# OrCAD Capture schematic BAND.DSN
size A
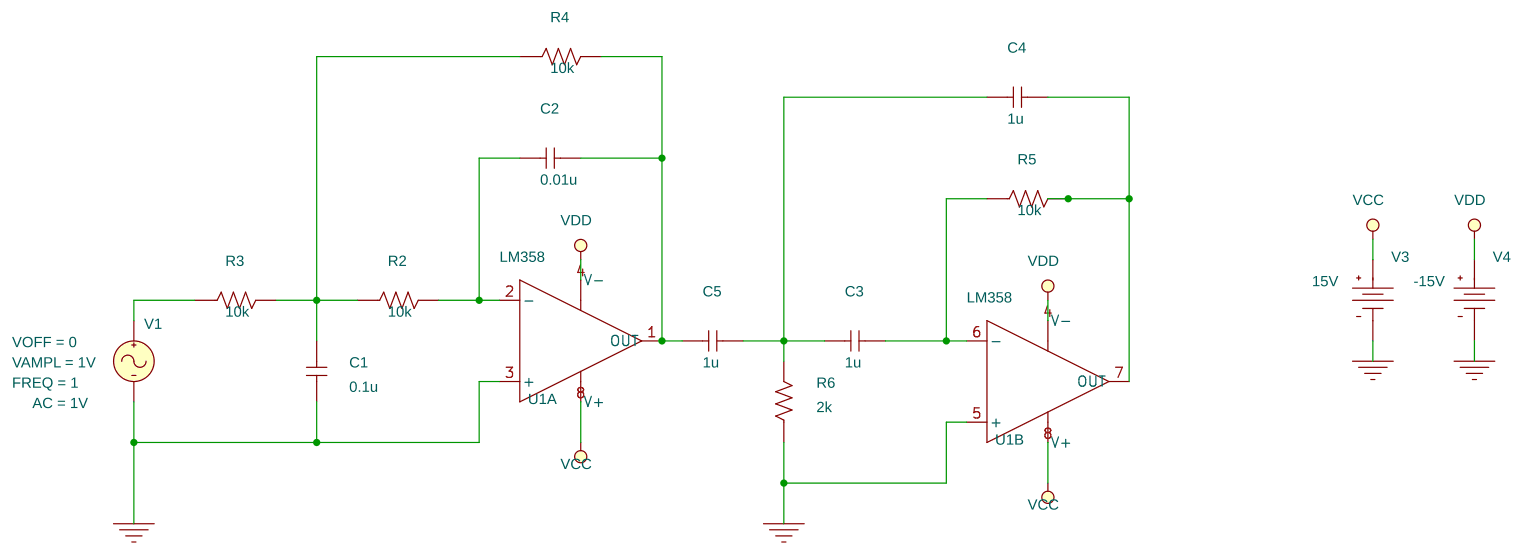
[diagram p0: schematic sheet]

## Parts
C1  0.1u  [cap196]
C2  0.01u  [cap196]
C3  1u  [cap196]
C4  1u  [cap196]
C5  1u  [cap196]
R2  10k  [AXRC05]
R3  10k  [AXRC05]
R4  10k  [AXRC05]
R5  10k  [AXRC05]
R6  2k  [AXRC05]
U1  LM358  [DIP1008W300L450]  (sections A,B)
V1  VSIN
V3  VDC
V4  VDC

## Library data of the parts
C1-C5 = C
R2-R6 = R
U1 = LM358
V1 = VSIN: AC: 1V; FREQ: 1; VAMPL: 1V; VOFF: 0
V3 = VDC: DC: 15V
V4 = VDC: DC: -15V

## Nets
VCC: U1.8(V+) V3.0(+)
VDD: U1.4(V-) V4.0(+)
0: C1.1 R6.1 U1.3(+) U1.5(+) V1.2(-) V3.1(-) V4.1(-)
N02800: C1.2 R2.1 R3.2 R4.1
N02810: C2.1 C5.2 R4.2 U1.1(OUT)
N02836: C2.2 R2.2 U1.2(-)
N02946: R3.1 V1.1(+)
N03821: C3.2 C4.2 C5.1 R6.2
N03831: C4.1 R5.2 U1.7(OUT)
N03863: C3.1 R5.1 U1.6(-)
